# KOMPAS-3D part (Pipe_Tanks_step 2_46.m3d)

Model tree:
1. X Axis
2. Y Axis
3. Z Axis  (labels: T-Bend Dn 50; Pipe Dn 50)
     Òîëùèíà ñòåíêè 1 = 1

Referenced files in C:\Documents and Settings\kashirsky\Мои документы\Camtasia Studio\Pipelines3D\Tanks\: Tanks_step 2.a3d
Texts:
  Pipe Dn 50
  Steel ASTM A295
  Three Point Plane
  Plane at Angle
  Line and Point Plane
  Axis through Two Vertices
  Axis of Feature
  Axis of Conical Surface
  Axis through Edge
  Trim by Surface
  Trim by Sketch
  Feature with No History
  Intersection Axis of Two Planes
  Two Line Plane
  Line and Face Plane
  Bend by line
  Hole in sheet body
  Cut in sheet body
  Point in CM
  Linear Dimension from Line to Point
  Surface Finish Symbol
  Geometric Tolerance Symbol
  Leader #1
  Leader #2
  Leader #3
  Shape Deviations and Datum
  Node point number
  Mark of coordination axis
  Node point designation
  Mark/Reference designation with leader
  Mark/reference designation on line
  Mark/Reference designation without leader
  T-Bend Dn 50
  Plane of section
